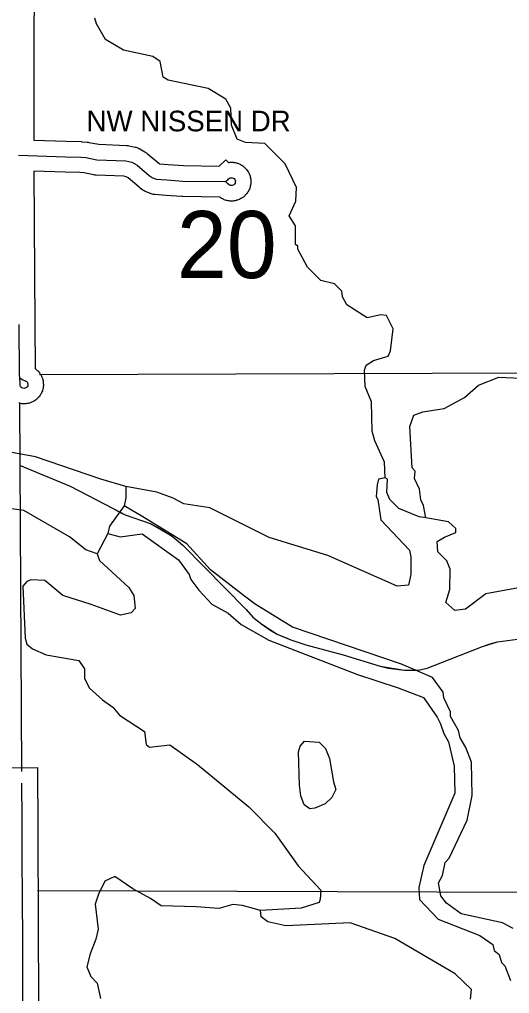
# Model space of a CAD drawing. Extents: x -1403959 to 81668, y -1400582 to 11018.
# Drawn here: x 6320.4 to 6412.2, y 9587.1 to 9769.7 of the extents above; entities that cross this region are included whole.
import ezdxf

# ---------------------------------------------------------------- set-up
doc = ezdxf.new("R2010")
doc.units = 0
for name, color, linetype in [('tdCiCoBndryTxt', 7, 'Continuous'), ('tdCiMapFrame', 7, 'Continuous'), ('tdCiSectLine', 7, 'Continuous'), ('tdCoCityStreetMajor', 7, 'Continuous'), ('tdCoClipBndry', 7, 'Continuous'), ('tdCoSectLinePart', 7, 'Continuous'), ('tdCoSectNmbr', 7, 'Continuous'), ('tdCoSurfBitum', 7, 'Continuous'), ('tdCoTwpNameTxt', 7, 'Continuous')]:
    doc.layers.add(name, color=color, linetype=linetype)

msp = doc.modelspace()

# ---------------------------------------------------------------- linework, layer by layer
at = {"layer": 'tdCiCoBndryTxt'}
for points in [[(6320.66, 9534.06), (6320.78, 9539.8), (6320.94, 9547.4), (6321.1, 9556.04), (6321.15, 9564.12), (6321.13, 9571.78), (6321.08, 9580.54), (6321.07, 9588.81), (6321.02, 9596.89), (6321, 9605.18), (6320.94, 9612.41), (6320.93, 9620.6), (6320.88, 9625.81)], [(6320.88, 9625.81), (6320.88, 9626.55)]]:
    msp.add_lwpolyline(points, dxfattribs=at)
at = {"layer": 'tdCiMapFrame'}
for points in [[(6320.21, 9744.27), (6329.06, 9743.99), (6331.89, 9743.92), (6332.87, 9743.84), (6334.9, 9743.43), (6340.33, 9743.21), (6341.47, 9742.95), (6342.43, 9742.4), (6344.71, 9740.47), (6345.24, 9740.09), (6346.01, 9739.79), (6348.03, 9739.64), (6351.04, 9739.43), (6358.85, 9739.33), (6359.07, 9739.41), (6359.27, 9739.53), (6359.45, 9739.67), (6359.6, 9739.84), (6359.74, 9739.96), (6359.91, 9740.03), (6360.1, 9740.06), (6360.28, 9740.04), (6360.45, 9739.98), (6360.61, 9739.88), (6360.73, 9739.74), (6360.82, 9739.57), (6360.86, 9739.4), (6360.85, 9739.21), (6360.8, 9739.03), (6360.71, 9738.87), (6360.58, 9738.74), (6360.43, 9738.64), (6360.25, 9738.59), (6360.06, 9738.58), (6359.88, 9738.62), (6359.72, 9738.7), (6359.46, 9738.89), (6359.23, 9739.1), (6359.01, 9739.33)], [(6320.48, 9702.55), (6320.76, 9702.34), (6321.05, 9702.16), (6321.37, 9702.01), (6321.54, 9701.96), (6321.7, 9701.87), (6321.84, 9701.74), (6321.93, 9701.58), (6321.98, 9701.4), (6321.99, 9701.22), (6321.95, 9701.04), (6321.86, 9700.87), (6321.74, 9700.74), (6321.58, 9700.64), (6321.41, 9700.58), (6321.22, 9700.57), (6321.04, 9700.6), (6320.88, 9700.68), (6320.73, 9700.8), (6320.63, 9700.95), (6320.56, 9701.13), (6320.55, 9701.31), (6320.57, 9701.49), (6320.48, 9702.55), (6320.48, 9702.55), (6320.44, 9703.12), (6320.36, 9712.55)]]:
    msp.add_lwpolyline(points, dxfattribs=at)
at = {"layer": 'tdCiSectLine'}
for points in [[(6323.14, 9771.83), (6323.13, 9768.93), (6323.11, 9754.49), (6323.12, 9754.49), (6323.1, 9751.6), (6323.11, 9747.09), (6329.14, 9746.89), (6331.97, 9746.82), (6332.08, 9746.81), (6332.12, 9746.81), (6333.1, 9746.73), (6333.25, 9746.72), (6333.43, 9746.68), (6335.25, 9746.32), (6340.46, 9746.11), (6340.52, 9746.1), (6340.71, 9746.08), (6340.9, 9746.05), (6340.96, 9746.04), (6342.1, 9745.79), (6342.22, 9745.76), (6342.4, 9745.7), (6342.58, 9745.63), (6342.76, 9745.56), (6342.92, 9745.47), (6342.93, 9745.46), (6343.89, 9744.91), (6344.05, 9744.81), (6344.2, 9744.7), (6344.31, 9744.61), (6346.49, 9742.76), (6346.63, 9742.66), (6346.66, 9742.65), (6348.24, 9742.53), (6351.16, 9742.33), (6357.85, 9742.25), (6359.08, 9743.43), (6359.58, 9742.92), (6359.64, 9742.93), (6359.72, 9742.94), (6359.91, 9742.95), (6360.1, 9742.96), (6360.29, 9742.95), (6360.37, 9742.95), (6360.55, 9742.93), (6360.66, 9742.92), (6360.85, 9742.89), (6361.03, 9742.84), (6361.21, 9742.79), (6361.26, 9742.77), (6361.43, 9742.71), (6361.56, 9742.66), (6361.74, 9742.58), (6361.91, 9742.49), (6362.07, 9742.39), (6362.08, 9742.39), (6362.23, 9742.28), (6362.37, 9742.18), (6362.52, 9742.06), (6362.66, 9741.93), (6362.77, 9741.81), (6362.9, 9741.67), (6362.91, 9741.65), (6363.03, 9741.51), (6363.14, 9741.35), (6363.24, 9741.19), (6363.31, 9741.07), (6363.39, 9740.91), (6363.42, 9740.86), (6363.5, 9740.69), (6363.56, 9740.51), (6363.62, 9740.33), (6363.64, 9740.23), (6363.68, 9740.05), (6363.7, 9739.96), (6363.73, 9739.77), (6363.75, 9739.58), (6363.76, 9739.4), (6363.76, 9739.33), (6363.75, 9739.15), (6363.75, 9739.02), (6363.73, 9738.83), (6363.7, 9738.64), (6363.66, 9738.46), (6363.65, 9738.43), (6363.6, 9738.25), (6363.55, 9738.1), (6363.48, 9737.92), (6363.41, 9737.75), (6363.32, 9737.59), (6363.23, 9737.43), (6363.22, 9737.42), (6363.12, 9737.26), (6363.01, 9737.11), (6362.89, 9736.96), (6362.79, 9736.85), (6362.66, 9736.72), (6362.63, 9736.69), (6362.5, 9736.56), (6362.35, 9736.44), (6362.19, 9736.33), (6362.1, 9736.27), (6361.94, 9736.17), (6361.88, 9736.13), (6361.71, 9736.04), (6361.54, 9735.96), (6361.36, 9735.9), (6361.28, 9735.87), (6361.1, 9735.82), (6361, 9735.79), (6360.81, 9735.74), (6360.63, 9735.71), (6360.44, 9735.69), (6360.39, 9735.69), (6360.21, 9735.68), (6360.06, 9735.68), (6359.87, 9735.68), (6359.69, 9735.7), (6359.5, 9735.73), (6359.49, 9735.74), (6359.3, 9735.77), (6359.13, 9735.81), (6358.95, 9735.87), (6358.77, 9735.94), (6358.62, 9736.01), (6358.45, 9736.09), (6358.43, 9736.1), (6358.27, 9736.18), (6358.11, 9736.28), (6357.96, 9736.39), (6357.89, 9736.44), (6351.01, 9736.53), (6350.85, 9736.54), (6350.85, 9736.54), (6347.84, 9736.74), (6347.81, 9736.74), (6345.79, 9736.89), (6345.63, 9736.91), (6345.44, 9736.94), (6345.26, 9736.99), (6345.07, 9737.04), (6344.94, 9737.09), (6344.17, 9737.39), (6344.13, 9737.41), (6343.95, 9737.49), (6343.79, 9737.58), (6343.63, 9737.68), (6343.55, 9737.73), (6343.02, 9738.11), (6342.94, 9738.17), (6342.83, 9738.26), (6340.76, 9740.02), (6340.41, 9740.22), (6339.95, 9740.32), (6334.78, 9740.54), (6334.71, 9740.54), (6334.53, 9740.56), (6334.34, 9740.59), (6332.47, 9740.96), (6331.74, 9741.02), (6328.98, 9741.09), (6328.97, 9741.09), (6323.13, 9741.28), (6323.26, 9712.57), (6323.33, 9704.27), (6323.47, 9704.17), (6323.62, 9704.05), (6323.73, 9703.94), (6323.86, 9703.82), (6323.89, 9703.79), (6324.02, 9703.65), (6324.14, 9703.5), (6324.25, 9703.35), (6324.32, 9703.23), (6324.42, 9703.08), (6324.45, 9703.03), (6324.53, 9702.86), (6324.61, 9702.69), (6324.68, 9702.51), (6324.72, 9702.4), (6324.77, 9702.22), (6324.79, 9702.15), (6324.83, 9701.97), (6324.86, 9701.78), (6324.88, 9701.59), (6324.88, 9701.49), (6324.89, 9701.3), (6324.89, 9701.22), (6324.89, 9701.03), (6324.87, 9700.84), (6324.84, 9700.65), (6324.82, 9700.57), (6324.78, 9700.39), (6324.75, 9700.29), (6324.7, 9700.1), (6324.63, 9699.93), (6324.55, 9699.75), (6324.52, 9699.69), (6324.43, 9699.53), (6324.38, 9699.42), (6324.28, 9699.26), (6324.16, 9699.11), (6324.04, 9698.96), (6324.01, 9698.92), (6323.88, 9698.78), (6323.79, 9698.69), (6323.65, 9698.56), (6323.5, 9698.43), (6323.35, 9698.32), (6323.32, 9698.3), (6323.16, 9698.2), (6323.03, 9698.12), (6322.87, 9698.03), (6322.69, 9697.96), (6322.52, 9697.89), (6322.5, 9697.88), (6322.32, 9697.82), (6322.16, 9697.78), (6321.97, 9697.73), (6321.79, 9697.7), (6321.6, 9697.68), (6321.59, 9697.68), (6321.41, 9697.67), (6321.22, 9697.66)], [(6321.22, 9697.66), (6321.03, 9697.67), (6320.84, 9697.69), (6320.67, 9697.72), (6320.49, 9697.75), (6320.48, 9697.76), (6320.29, 9697.8)], [(6317.95, 9629.43), (6323.76, 9629.47), (6323.78, 9626.57), (6323.83, 9620.62), (6323.83, 9620.61), (6323.84, 9612.43), (6323.91, 9605.2), (6323.91, 9605.18), (6323.92, 9596.9), (6323.97, 9588.83), (6323.97, 9588.82), (6323.99, 9580.55)]]:
    msp.add_lwpolyline(points, dxfattribs=at)
at = {"layer": 'tdCoCityStreetMajor'}
for points in [[(6324.16, 9703.14), (6416.13, 9703.49)], [(6320.43, 9697.83), (6320.78, 9628.71)], [(6323.79, 9606.43), (6417.33, 9606.13)]]:
    msp.add_lwpolyline(points, dxfattribs=at)
at = {"layer": 'tdCoClipBndry'}
msp.add_lwpolyline([(6320.39, 9686.18), (6329.92, 9682.23), (6337.94, 9678.02), (6340.23, 9676.87), (6344.9, 9675.26), (6349.02, 9672.88), (6351.02, 9671.18), (6362.9, 9659.1), (6364.14, 9657.69), (6365.81, 9656.33), (6368.69, 9654.47), (6371.24, 9653.39), (6374.05, 9652.45), (6381.06, 9650.6), (6387.97, 9648.5), (6392.57, 9647.73), (6395.17, 9647.75), (6396.78, 9648.1), (6407.16, 9652.2), (6409.99, 9653.03), (6414.67, 9653.65)], dxfattribs=at)
at = {"layer": 'tdCoSurfBitum'}
for points in [[(6388.92, 9683.82), (6388.78, 9686.72), (6386.96, 9690.7), (6386.51, 9692.53), (6386.38, 9698.03), (6385.16, 9700.93), (6385.02, 9703.99), (6385.33, 9704.9), (6386.71, 9705.81), (6389.46, 9706.57), (6389.92, 9707.63), (6390.39, 9711.75), (6389.18, 9714.2), (6388.11, 9714.36), (6385.52, 9713.76), (6381.71, 9716.21), (6380.95, 9717.74), (6380.8, 9718.81), (6379.43, 9720.19), (6376.84, 9720.81), (6374.4, 9723.26), (6372.58, 9726.63), (6372.58, 9727.24), (6372.13, 9727.55), (6372.14, 9731.06), (6370.93, 9732.89), (6372.16, 9735.64), (6372.32, 9738.23), (6370.2, 9742.67), (6366.39, 9746.5), (6362.73, 9746.66), (6361.2, 9747.28), (6360.14, 9749.88), (6360, 9753.08), (6359.09, 9754.77), (6355.74, 9756.76), (6348.26, 9758.32), (6347.35, 9758.93), (6346.75, 9761.84), (6345.38, 9762.76), (6339.89, 9764), (6336.53, 9766), (6334.87, 9768.9), (6334.56, 9769.97)], [(6340.36, 9682.17), (6335.63, 9683.57), (6323.43, 9687.73), (6319, 9688.51), (6314.58, 9690.51), (6301.77, 9693.92), (6283.45, 9695.52), (6268.35, 9699.08), (6263.31, 9698.65), (6262.09, 9699.41), (6261.79, 9700.64), (6260.27, 9702.78), (6257.83, 9703.55), (6251.42, 9703.73), (6250.19, 9702.97), (6250.34, 9701.6), (6250.8, 9700.98), (6250.94, 9699.3), (6248.8, 9697.78), (6242.53, 9695.98), (6236.27, 9694.93), (6232.03, 9694.69)], [(6415.26, 9663.42), (6407.78, 9662.07), (6403.95, 9659.19), (6401.96, 9658.89), (6400.29, 9660.42), (6401.06, 9662.86), (6401.08, 9666.68), (6400.47, 9668.21), (6398.8, 9669.89), (6398.65, 9671.88), (6400.03, 9672.64), (6402.17, 9673.54), (6402.17, 9674.31), (6400.8, 9675.53), (6396.53, 9676.31), (6396.08, 9678.61), (6395.62, 9679.68), (6395.33, 9681.66), (6394.42, 9683.65), (6394.57, 9685.02), (6393.97, 9685.64), (6393.54, 9693.42), (6394.31, 9695.56), (6395.99, 9696.16), (6399.96, 9696.76), (6403.79, 9698.88), (6406.39, 9701.16), (6410.21, 9702.67), (6421.2, 9702.17)], [(6388.92, 9683.82), (6387.7, 9683.52), (6387.39, 9682.45), (6387.23, 9680.32), (6387.53, 9679.71), (6388.13, 9675.89), (6393.45, 9670.22), (6393.75, 9669), (6393.74, 9665.64), (6393.28, 9663.66), (6391.14, 9663.51), (6378.18, 9669.21), (6367.2, 9672.61), (6356.07, 9678.15), (6351.19, 9678.93), (6349.21, 9680), (6346.16, 9681.08), (6340.36, 9682.17)], [(6396.53, 9676.31), (6395.31, 9676.47), (6391.5, 9678.01), (6389.82, 9679.7), (6389.22, 9681.07), (6389.38, 9683.52), (6388.92, 9683.82)], [(6340.36, 9682.17), (6340.35, 9680.04), (6340.04, 9678.51)], [(6334.97, 9669.52), (6332.83, 9670.3), (6329.79, 9672.75), (6321.26, 9677.67), (6307.21, 9679.55)], [(6412.91, 9599.29), (6410.93, 9600.36), (6403.15, 9602.07), (6400.41, 9604.07), (6399.34, 9605.45), (6398.89, 9607.89), (6399.66, 9609.26), (6400.13, 9611.7), (6400.89, 9612.47), (6404.28, 9619.63), (6405.21, 9624.21), (6405.08, 9630.47), (6404.02, 9633.22), (6402.96, 9635.05), (6402.66, 9636.43), (6401.14, 9639.03), (6401.14, 9639.95), (6399.93, 9642.55), (6399.78, 9643.62), (6397.8, 9646.37), (6392.01, 9648.84), (6371.57, 9655.79), (6364.56, 9660.1), (6362.58, 9661.63), (6356.18, 9666.54), (6351.77, 9671.44), (6343.54, 9676.51), (6340.04, 9678.51), (6337.28, 9674.71), (6336.97, 9673.33), (6339.26, 9672.71), (6343.38, 9673.31), (6350.23, 9668.4), (6352.21, 9665.64), (6352.51, 9664.73), (6354.03, 9662.73), (6356.46, 9660.13), (6359.51, 9658.44), (6361.95, 9656.29), (6367.13, 9653.37), (6383.75, 9646.9), (6391.38, 9644.43), (6396.1, 9642.58), (6398.69, 9638.9), (6399.29, 9637.68), (6399.9, 9635.85), (6400.81, 9634.32), (6401.86, 9629.73), (6401.99, 9624.7), (6396.14, 9611.13), (6395.21, 9607.01), (6395.36, 9604.72), (6398.86, 9601.05), (6406.63, 9597.96), (6409.07, 9596.27), (6409.37, 9595.2), (6410.29, 9594.44), (6410.74, 9592.91), (6411.35, 9592.3), (6412.41, 9589.54)], [(6336.97, 9673.33), (6334.97, 9669.52)], [(6334.97, 9669.52), (6335.42, 9668.3), (6340.9, 9663.24), (6341.81, 9661.71), (6342.11, 9659.27), (6341.34, 9658.51), (6339.36, 9658.06), (6333.87, 9660.06), (6328.53, 9661.76), (6325.18, 9664.52), (6322.58, 9664.69), (6321.82, 9664.38), (6321.05, 9663.47), (6321.48, 9653.7), (6321.78, 9652.63), (6322.84, 9651.71), (6325.43, 9650.63), (6331.54, 9649.54), (6332.6, 9648.01), (6332.6, 9646.18), (6333.51, 9644.34), (6335.94, 9642.19), (6337.92, 9640.81), (6339.14, 9639.28), (6343.86, 9636.21), (6344.16, 9633.77), (6344.76, 9633.31), (6348.58, 9633.75), (6353.76, 9630.07), (6363.35, 9622.09), (6368.22, 9617.19), (6372.63, 9611.07), (6376.89, 9606.47), (6376.73, 9604.79), (6376.57, 9604.18), (6373.21, 9603.13), (6365.58, 9602.7)], [(6374.8, 9621.74), (6373.74, 9622.51), (6373.13, 9624.19), (6372.84, 9626.18), (6372.7, 9632.44), (6373.01, 9633.51), (6373.78, 9634.42), (6376.53, 9634.26), (6377.75, 9633.03), (6378.5, 9631.2), (6379.25, 9626.77), (6379.7, 9625.39), (6378.93, 9623.87), (6377.71, 9622.65), (6375.72, 9621.89), (6374.8, 9621.74)], [(6404.91, 9586.06), (6405.07, 9587.89), (6402.03, 9590.81), (6390.75, 9597.41), (6382.36, 9600.34), (6370.3, 9599.78), (6366.94, 9600.55), (6365.72, 9601.48), (6365.58, 9602.7), (6362.22, 9603.63), (6360.39, 9603.79), (6357.79, 9603.03), (6353.51, 9603.35), (6346.95, 9603.53), (6344.97, 9604.91), (6341.62, 9606.76), (6338.27, 9609.06), (6336.43, 9608.15), (6335.2, 9605.71), (6334.58, 9603.88), (6335.18, 9599.15), (6334.71, 9597.32), (6333.63, 9594.57), (6333.01, 9592.13), (6333.77, 9590.3), (6334.99, 9589.07), (6335.59, 9586.17)]]:
    msp.add_lwpolyline(points, dxfattribs=at)
at = {"layer": 'tdCoTwpNameTxt'}
msp.add_lwpolyline([(6320.39, 9686.18), (6329.92, 9682.23), (6337.94, 9678.02), (6339.28, 9677.28), (6340.23, 9676.87), (6344.9, 9675.26), (6346.33, 9674.51), (6349.02, 9672.88), (6351.02, 9671.18), (6362.9, 9659.1), (6364.14, 9657.69), (6365.81, 9656.33), (6367.34, 9655.29), (6368.69, 9654.47), (6370.22, 9653.87), (6371.24, 9653.39), (6374.05, 9652.45), (6381.06, 9650.6), (6387.97, 9648.5), (6389.5, 9648.12), (6392.57, 9647.73), (6395.17, 9647.75), (6396.78, 9648.1), (6407.16, 9652.2), (6408.56, 9652.67), (6409.99, 9653.03), (6414.67, 9653.65)], dxfattribs=at)

# ---------------------------------------------------------------- texts
at = {"layer": 'tdCoSectLinePart'}
msp.add_text('20', height=12.575, rotation=359.9891, dxfattribs=at).set_placement((6349.9, 9721.24))
at = {"layer": 'tdCoSectNmbr'}
msp.add_text('NW NISSEN DR', height=3.8691, dxfattribs=at).set_placement((6332.98, 9748.75))

doc.saveas('drawing.dxf')
